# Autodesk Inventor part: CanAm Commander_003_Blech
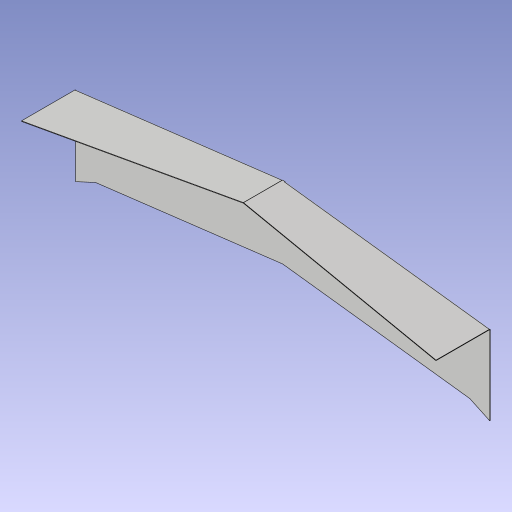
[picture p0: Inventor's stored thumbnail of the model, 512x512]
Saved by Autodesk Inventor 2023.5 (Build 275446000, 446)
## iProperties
Part Number: CanAm Commander_003_Blech
Material: Generisch
Document SubType Name: Blech
Designer: wondraschek
Density: 1 g/cm^3
Sheet Metal Rule: Standard_mm
Appearance: Vorgabe
Flat Pattern Width: 13.7047 cm
Flat Pattern Length: 37.9407 cm
Flat Pattern Area: 519.968 cm^2
Sheet Metal Width: 137,047 mm
Sheet Metal Length: 379,407 mm
Sheet Metal Area: 51996,778 mm^2
Author: wondraschek
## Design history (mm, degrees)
derived "CanAm Commander_SKI.ipt"
sketch "Skizze1"
  geometry: L1 (-183.976, 41.507)-(-350.197, 61.917) reference; L2 (-350.197, 61.917)-(-367.951, 70.196) reference; L3 (-367.951, 70.196)-(-367.951, 0) reference; L4 (-367.951, 0)-(-183.976, -22.589) reference; L5 (0, 0)-(-183.976, -22.589) reference; L6 (-17.754, 61.917)-(-183.976, 41.507) reference; L7 (0, 70.196)-(-17.754, 61.917) reference; L8 (0, 70.196)-(0, 0) reference; 1 further point
sketch "Skizze2"
  geometry: L1 (0, 0)-(0, 47.836) reference; L2 (185.357, 13.042)-(0, 0) reference; L3 (0, 47.836)-(185.357, 47.836) reference; L4 (185.357, 13.042)-(185.357, 47.836) reference; 1 further point
sketch "Skizze3"
  geometry: L1 (0, 47.836)-(-185.357, 47.836) reference; L2 (-185.357, 13.042)-(-185.357, 47.836) reference; L3 (-185.357, 13.042)-(0, 0) reference; L4 (0, 0)-(0, 47.836) reference; 1 further point
node "Fläche1"
node "Fläche4"
node "Fläche5"
node "Volumenkörper1"
tag "Bezeichnung1"
feature "Grobblech1" dims "d1" = 0.5 (= Stärke)
feature "Grobblech4" dims "d1" = 0.5 (= Stärke), "d34" = 0.5 (= Biegeradius), "d35" = 0.5 (= BreiteBiegungsfreistellung), "d37" = 1 (= MinimalRest)
feature "Biegung7" dims "d1" = 0.5 (= Stärke), "d34" = 0.5 (= Biegeradius), "d35" = 0.5 (= BreiteBiegungsfreistellung), "d36" = 0.25 (= TiefeBiegungsfreistellung), "d37" = 1 (= MinimalRest), "d38" = 0.5 (= Übergangsradius), "AbstandVerbindung" = 0.01
feature "Grobblech5" dims "d1" = 0.5 (= Stärke), "d39" = 0.5 (= Biegeradius), "d40" = 0.5 (= BreiteBiegungsfreistellung), "d42" = 1 (= MinimalRest)
feature "Biegung8" dims "d1" = 0.5 (= Stärke), "d39" = 0.5 (= Biegeradius), "d40" = 0.5 (= BreiteBiegungsfreistellung), "d41" = 0.25 (= TiefeBiegungsfreistellung), "d42" = 1 (= MinimalRest), "d43" = 0.5 (= Übergangsradius), "AbstandVerbindung" = 0.01
feature "Volumenkörper1::CanAm Commander_SKI.ipt"
node "Flä1"
feature "Definition1"
other parameters: "Stärke" = 0.5 (derived), "KFaktor" = 4.4, "Biegeradius" = 0.5 (= Stärke), "BreiteBiegungsfreistellung" = 0.5 (= Stärke), "TiefeBiegungsfreistellung" = 0.25 (= 0.5 x Stärke), "GrößeEckenfreistellung" = 2 (= 4 x Stärke), "MinimalRest" = 1 (= 2 x Stärke), "Übergangsradius" = 0.5 (= Biegeradius), "JacobiRadiusGröße" = 0.5 (= Biegeradius), "Abstandsgröße" = 0.5 (= Stärke), "Abstandsgröße" = 0.5, "Biegeradius" = 0.5, "BreiteBiegungsfreistellung" = 0.5, "GrößeEckenfreistellung" = 2, "JacobiRadiusGröße" = 0.5, "MinimalRest" = 1, "Stärke" = 0.5, "TiefeBiegungsfreistellung" = 0.25, "Übergangsradius" = 0.5
